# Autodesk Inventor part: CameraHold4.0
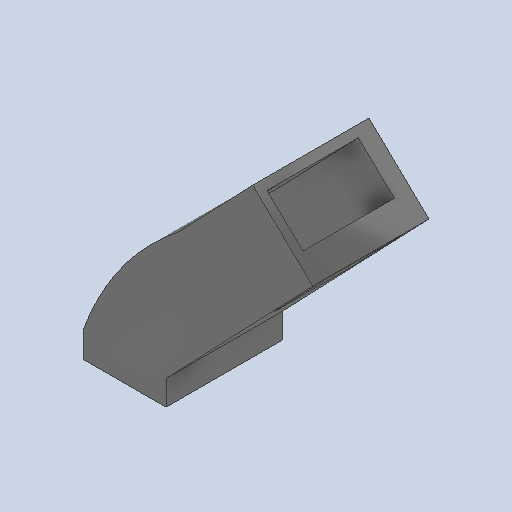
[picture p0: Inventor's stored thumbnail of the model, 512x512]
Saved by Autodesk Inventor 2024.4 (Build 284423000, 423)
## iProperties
Created: 2025-05
Part Number: CameraHold4.0
Material: Generic
Document SubType Name: Modeling
Designer: AdminForWorker
Density: 1 g/cm^3
Appearance: Default
Title: CameraHold4.0 v2
Author: AdminForWorker
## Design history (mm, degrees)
feature "Body1"
body "Solid1"
